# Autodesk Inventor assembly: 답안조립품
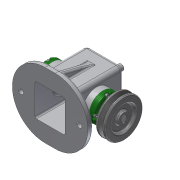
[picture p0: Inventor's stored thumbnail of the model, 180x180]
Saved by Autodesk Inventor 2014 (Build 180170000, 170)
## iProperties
Created: 2017-07
Part Number: 답안조립품
Document SubType Name: Assembly
Designer: user
Author: user
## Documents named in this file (16)
- C:\Users\user\Desktop\470708V1011\답안조립품.iam
- C:\Users\user\Desktop\470708V1011\V벨트풀리.ipt
- C:\Users\user\Desktop\470708V1011\고정핀 1.2 x  8.ipt
- C:\Users\user\Desktop\470708V1011\뒤커버.ipt
- C:\Users\user\Desktop\470708V1011\링크.ipt
- C:\Users\user\Desktop\470708V1011\멈춤나사 M3x8.ipt
- C:\Users\user\Desktop\470708V1011\베어링 12 x 32 x 10.ipt
- C:\Users\user\Desktop\470708V1011\본체.ipt
- C:\Users\user\Desktop\470708V1011\볼트 M4 x 12.ipt
- C:\Users\user\Desktop\470708V1011\부시.ipt
- C:\Users\user\Desktop\470708V1011\슬라이드.ipt
- C:\Users\user\Desktop\470708V1011\앞커버.ipt
- C:\Users\user\Desktop\470708V1011\오일실 12 25 7.ipt
- C:\Users\user\Desktop\470708V1011\키 4 x 4 x 10.ipt
- C:\Users\user\Desktop\470708V1011\편심축.ipt
- C:\Users\user\Desktop\470708V1011\핀 5 x 18.ipt
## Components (3 placed, 3 different names)
1. V벨트풀리:1
2. 고정핀 1.2 x  8:1
3. 핀 5 x 18:1
